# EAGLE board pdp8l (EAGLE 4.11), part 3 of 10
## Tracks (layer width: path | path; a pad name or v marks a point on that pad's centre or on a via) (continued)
F_SET  (via drill 0.61) (continued)
  Route15 0.203: v196.7,124.61 v196.7,126.24 | v351.94,103.89 335.28,120.55 335.28,120.95 334.87,121.36 333.65,121.36 329.59,125.42 329.59,127.05 327.15,129.49 327.15,133.55 321.46,139.24 319.84,139.24 302.77,156.31 302.36,156.31 301.95,156.72 301.95,157.94 v287.73,172.16
  Bottom 0.203: v355.19,50.65 351.54,50.65 D09.F1 | C07.N2 369.42,102.26 365.76,102.26 364.95,103.07 362.1,103.07 360.88,104.29 C08.M2 359.66,104.7 359.26,104.29 355.6,104.29 354.79,103.48 352.35,103.48 v351.94,103.89 | v196.7,124.61 196.29,125.02 128.83,125.02 126.39,122.58 109.32,122.58 108.51,121.77 104.04,121.77 103.63,121.36 C28.F2 | v196.7,126.24 197.1,125.83 239.37,125.83 v242.21,128.68
F_SET\  (via drill 0.61)
  Top 0.203: D17.S2 245.47,22.61 245.47,23.01 243.43,25.04 D17.R2 243.43,25.86 244.65,27.08 244.65,49.02 v247.09,51.46 | v372.67,107.14 372.67,105.51 C07.M2
  Route2 0.203: v332.03,125.02 331.22,124.21 329.18,124.21 C11.E1 327.96,123.39 326.75,122.17 324.71,122.17 321.06,118.52 318.62,118.52 318.21,118.11 318.21,117.7 312.93,112.42 308.86,112.42 303.17,106.73 301.55,106.73 288.95,94.13 288.95,93.32 v247.09,51.46
  Route15 0.203: v332.03,125.02 335.69,125.02 v353.16,107.54
  Bottom 0.203: v353.16,107.54 353.97,106.73 365.35,106.73 367.79,109.17 370.64,109.17 v372.67,107.14
FEED_HOLE  (via drill 0.61)
  Top 0.203: v60.96,142.9 61.77,143.71 v61.77,150.22
  Route2 0.203: v60.96,142.9 60.96,142.49 57.3,138.84 57.3,138.02 56.9,137.62 56.9,135.59 27.23,105.92 27.23,102.26 C34.N2 | v61.77,150.22 62.18,150.22 79.25,167.28 79.25,169.72 80.47,170.94 AB30.BM2
FETCH  (via drill 0.61)
  Top 0.203: B09.B1 350.32,199.39 350.32,194.11 B09.D1 351.13,192.89 352.75,191.26 352.75,190.04 355.19,187.6 | 355.19,187.6 355.19,192.07 354.38,192.89 354.38,196.14 B09.C1 353.57,197.36 353.57,202.64 B09.A1 353.97,203.86 v353.97,216.05 | 355.19,187.6 355.19,181.1 358.44,177.85 358.44,164.85 359.26,164.03 359.26,160.38 358.44,159.56 358.44,136.4 359.66,135.18 359.66,132.74 358.85,131.93 358.85,115.27 361.7,112.42 361.7,99.82 360.88,99.01 C08.P2 | v314.55,216.05 314.15,216.46 314.15,255.88 313.33,256.69 A12.F1
  Bottom 0.203: v353.97,216.05 v314.55,216.05
FETCH\  (via drill 0.61)
  Route2 0.203: v366.17,103.07 362.92,103.07 358.04,98.2 358.04,96.98 357.63,96.57 357.63,95.76 C08.R2
  Bottom 0.203: v366.17,103.07 376.73,103.07 379.98,99.82 411.68,99.82 412.09,100.23 447.04,100.23 448.67,98.6 C01.P2
GND  (via drill 0.61)
  Top 0.508: v441.35,64.47 441.35,83.16 440.54,83.97 440.54,88.04 440.13,88.44 C02.T1 | D16.C2 258.47,59.59 258.47,54.71 D16.E2 258.88,53.49 258.88,49.84 261.31,47.4 261.31,44.96 D16.J1 261.72,43.74 260.5,42.52 260.5,37.24 260.1,36.83 | 260.1,36.83 258.88,35.61 D16.M2 | 263.35,29.11 260.1,29.11 260.1,36.83 | 263.35,29.11 264.57,29.11 D16.P1 | 263.35,29.11 263.35,20.98 262.13,19.76 D16.T1 | C04.P1 417.37,97.79 415.75,96.16 415.75,93.73 414.53,92.51 414.53,89.66 C04.T1 | C06.J1 388.52,114.86 388.52,117.3 387.3,118.52 387.3,124.61 386.08,125.83 386.08,129.49 C06.C2 | C04.C2 410.87,129.49 410.87,124.61 C04.E2 411.68,123.39 412.5,122.58 412.5,116.48 414.12,114.86 C04.J1 414.12,113.64 412.9,112.42 412.9,107.14 411.28,105.51 C04.M2 411.68,104.29 411.68,100.23 v412.5,99.42 | AB02.BD1 439.73,192.89 439.73,188.01 AB02.BF1 | AB02.BE2 436.47,191.26 436.47,196.14 AB02.BC2 | AB07.BD1 375.92,192.89 375.92,188.01 AB07.BF1 | AB07.BC2 372.67,196.14 372.67,191.26 AB07.BE2 | AB06.BF2 383.24,187.6 385.27,189.64 385.27,190.04 AB06.BE2 385.67,191.26 385.67,196.14 AB06.BC2 | AB05.BB2 395.83,200.61 396.65,201.42 397.46,201.42 398.27,200.61 398.27,197.36 AB05.BC2 398.27,196.14 398.27,191.26 AB05.BE2 | AB05.BD1 401.52,192.89 401.52,188.01 AB05.BF1 | AB03.BC2 423.47,196.14 423.47,191.26 AB03.BE2 | AB04.BF1 414.93,186.79 416.97,184.76 AB04.BH1 416.97,183.54 415.75,182.32 415.75,172.97 414.53,171.75 414.53,168.91 AB04.BN1 | AB04.BC2 410.87,196.14 410.87,191.26 AB04.BE2 | AB05.BH1 405.59,184.35 407.62,186.38 407.62,186.79 AB04.BF2 | AB05.BN1 401.12,167.69 401.12,163.63 400.3,162.81 400.3,159.97 401.52,158.75 401.52,156.31 AB05.BT1
  Top 0.508: C12.C2 310.08,130.71 310.9,131.52 310.9,144.12 310.49,144.53 310.49,151.03 312.52,153.06 312.52,155.09 B12.T1 | v327.56,61.62 327.15,62.03 327.15,84.38 325.93,85.6 325.93,88.44 C11.T1 | B36.R2 1.22,162.41 1.22,167.69 B36.N2 1.22,168.91 1.22,174.19 B36.L2 1.22,175.41 1.22,180.29 B36.J2 1.22,181.51 1.22,186.79 B36.F2 | B36.N1 7.72,167.69 7.72,162.41 B36.R1 7.72,161.19 7.72,156.31 B36.T1 8.53,155.09 8.94,154.69 8.94,151.03 10.97,149 10.97,137.21 C36.A1 10.97,135.99 10.97,130.71 C36.C1 10.97,129.49 9.35,127.86 9.35,125.42 8.13,124.21 8.13,121.36 C36.F1 | B35.F2 13.82,186.79 13.82,181.51 B35.J2 | B34.N2 26.42,167.69 26.42,162.41 B34.R2 | B35.T1 20.32,156.31 20.32,161.19 B35.R1 | B35.N2 13.82,167.69 13.82,162.41 B35.R2 | B34.L2 26.82,175.41 26.82,180.29 B34.J2 26.42,181.51 26.42,186.79 B34.F2 | B33.J2 39.42,180.29 39.42,175.41 B33.L2 39.42,174.19 39.42,168.91 B33.N2 | B34.K1 36.98,178.26 39.01,180.29 39.01,180.7 B33.J2 | B34.T1 32.92,156.31 32.92,161.19 B34.R1 32.92,162.41 32.92,167.69 B34.N1 | B33.F2 39.42,186.79 39.42,181.51 B33.J2 | B32.T1 58.93,156.31 58.93,161.19 B32.R1 58.52,162.41 58.52,167.69 B32.N1 58.93,168.91 60.15,170.13 60.15,175.41 61.77,177.04 B32.K1 | B33.T1 45.92,156.31 45.92,161.19 B33.R1 45.52,162.41 45.52,167.69 B33.N1 | B32.N2 52.02,168.91 52.02,174.19 B32.L2 52.02,175.41 52.02,180.29 B32.J2 52.02,181.51 52.02,186.79 B32.F2 | B28.D2 102.82,192.89 102.82,188.01 B28.F2 | B36.A1 10.57,202.64 10.57,197.36 B36.C1 10.97,196.14 10.97,195.73 9.75,194.51 9.75,189.64 8.13,188.01 B36.F1 | B35.A1 23.57,202.64 23.57,197.36 B35.C1
  Top 0.508: B32.A1 61.77,202.64 61.77,197.36 B32.C1 | B33.C1 48.77,197.36 48.77,202.64 B33.A1 49.17,203.86 49.17,215.24 47.55,216.86 47.55,224.18 46.74,224.99 A33.T1 | B34.A1 36.17,202.64 36.17,197.36 B34.C1 | 120.7,36.83 119.48,35.61 D27.M2 | 120.7,36.83 120.7,42.52 121.92,43.74 D27.J1 | D28.V1 110.13,13.26 112.17,15.29 D28.U1 | 110.95,17.73 112.17,16.51 112.17,16.1 D28.U1 | 110.95,17.73 110.13,18.54 D28.T1 | 110.95,17.73 110.95,26.26 112.57,27.89 D28.P1 | D27.T2 115.42,18.54 113.39,16.51 113.39,16.1 D28.U1 | D27.V1 122.73,13.26 124.77,15.29 124.77,15.7 D27.U1 124.77,16.1 124.77,16.51 123.55,17.73 | 123.55,17.73 122.73,18.54 D27.T1 | 123.55,17.73 123.55,26.26 125.17,27.89 D27.P1 125.17,29.11 125.17,32.36 120.7,36.83 | v149.15,62.84 149.15,67.31 149.96,68.12 149.96,83.16 148.74,84.38 148.74,88.04 148.34,88.44 C25.T1 | D29.A1 99.57,66.09 99.57,60.81 D29.C1 100.38,59.59 101.6,58.37 101.6,49.02 | D30.A1 86.97,66.09 86.97,60.81 D30.C1 | 101.6,49.02 101.6,42.93 100.38,41.71 D29.K1 | 101.6,49.02 102.82,50.24 D28.F2 | D30.K1 87.78,40.89 89.81,38.86 89.81,38.46 D29.L2 | D29.L2 90.22,38.86 90.22,43.74 D29.J2 90.22,44.96 90.22,50.24 D29.F2 | D30.L2 77.62,38.86 77.62,43.74 D30.J2 77.22,44.96 77.22,50.24 D30.F2 78.44,50.65 83.72,50.65 D30.F1 | D29.T1 96.72,19.76 96.72,24.64 D29.R1 96.32,25.86 96.32,31.14 D29.N1 | D31.T1 71.93,19.36 76.4,19.36 76.4,23.42 77.62,24.64 D30.R2 77.62,25.86 77.62,31.14 D30.N2 | D30.U2 81.69,16.1 83.72,18.14 83.72,18.54 D30.T1 84.12,19.76 84.12,24.64 D30.R1 83.72,25.86 83.72,31.14 D30.N1 | D29.L2 90.22,37.64 90.22,32.36 D29.N2 | D31.C2 68.68,60.81 69.9,62.03 69.9,87.22 71.12,88.44 C31.T1
  Top 0.508: D32.D1 58.93,56.34 60.15,55.12 60.15,20.98 58.93,19.76 D32.T1 58.12,18.54 54.05,18.54 54.05,12.04 53.24,11.23 34.95,11.23 34.95,13.66 31.7,16.92 | D36.U2 5.28,16.51 7.32,18.54 D36.T1 7.72,19.76 7.72,24.64 D36.R1 | D36.R1 7.32,25.04 2.03,25.04 D36.R2 1.22,25.86 1.22,31.14 D36.N2 1.22,32.36 1.22,37.64 D36.L2 1.22,38.86 1.22,43.74 D36.J2 1.22,44.96 1.22,50.24 D36.F2 2.03,51.46 3.25,52.68 3.25,58.37 4.47,59.59 D36.C2 | D36.R1 7.72,25.86 7.72,31.14 D36.N1 8.13,32.36 9.35,33.58 9.35,38.86 10.97,40.49 D36.K1 | 31.7,16.92 32.92,18.14 32.92,18.54 D34.T1 33.33,19.76 33.33,24.64 D34.R1 32.92,25.86 32.92,31.14 D34.N1 | 31.7,16.92 30.89,16.1 D34.U2 | D35.U2 17.88,16.51 19.91,18.54 19.91,18.95 D35.T1 20.32,19.76 20.32,24.64 D35.R1 19.91,25.04 15.04,25.04 D35.R2 13.82,25.86 13.82,31.14 D35.N2 | D35.J2 14.22,43.74 14.22,38.86 D35.L2 13.82,37.64 13.82,32.36 D35.N2 | D35.N2 15.04,31.55 19.91,31.55 D35.N1 | D34.N2 26.82,31.14 26.82,25.86 D34.R2 | D34.A1 36.17,66.09 36.17,60.81 D34.C1 | D36.A1 10.57,66.09 10.57,60.81 D36.C1 | D35.C1 23.57,60.81 23.57,66.09 D35.A1 23.57,67.31 17.88,73 17.88,85.19 C35.U2 17.88,86.41 19.91,88.44 19.91,88.85 C35.T1 20.32,89.66 20.32,94.54 C35.R1 | D34.L2 26.42,38.46 24.38,40.49 24.38,40.89 D35.K1 24.38,41.71 24.38,42.11 26.42,44.15 D34.J2 26.42,44.96 26.42,50.24 D34.F2 | D34.K1 36.17,41.71 34.95,42.93 34.95,49.02 33.73,50.24 D34.F1 | C35.A1 23.57,135.99 23.57,130.71 C35.C1 | C36.F2 1.22,120.14 1.22,114.86 C36.J2 1.63,113.64 1.63,108.76 C36.L2 1.63,107.14 1.63,102.26 C36.N2 1.22,101.04 1.22,95.76 C36.R2 2.03,94.94 7.32,94.94 C36.R1
  Top 0.508: C36.N1 7.72,101.04 7.72,95.76 C36.R1 | C36.T1 7.72,89.66 7.72,94.54 C36.R1 | C35.N2 14.22,102.26 14.22,107.14 C35.L2 13.82,108.36 11.79,110.39 11.79,110.79 C36.K1 11.79,111.61 13.82,113.64 C35.J2 13.82,114.86 13.82,120.14 C35.F2 | 124.36,84.78 124.77,85.19 124.77,85.6 C27.U1 124.77,86 124.77,86.41 122.73,88.44 C27.T1 122.33,89.66 122.33,91.29 125.17,94.13 125.17,97.79 C27.P1 | 124.36,84.78 122.73,83.16 C27.V1 | C27.M2 119.48,105.51 120.7,106.73 120.7,109.98 121.92,111.2 121.92,113.64 C27.J1 121.92,114.86 121.11,115.67 121.11,118.11 119.48,119.74 119.48,123.39 C27.E2 119.08,124.61 119.08,129.49 C27.C2 | B24.T1 159.72,155.09 158.5,153.87 158.5,131.52 157.68,130.71 C24.C2 | 124.36,84.78 124.36,80.72 123.95,80.31 123.95,61.62 124.77,60.81 D27.C1 | AB05.AB2 395.83,269.29 397.87,267.26 AB05.AC2 | AB06.AB2 383.24,269.7 385.27,267.67 385.27,267.26 AB06.AC2 | AB07.AB2 370.23,269.29 372.26,267.26 372.26,266.85 AB07.AC2 | A10.J1 337.72,251.41 336.91,252.22 336.91,256.29 336.5,256.69 336.5,264.82 335.28,266.04 A10.C2 | 247.9,242.47 249.12,243.69 A17.L1 | 247.9,242.47 247.9,227.43 249.12,226.21 A17.T1 | 247.9,242.47 247.9,264.41 246.28,266.04 A17.C2 | A28A.E2 105.66,260.76 103.63,262.79 103.63,263.2 A28A.D2 103.63,264.01 103.63,264.41 105.66,266.45 A28A.C2 | A25.E2 145.09,260.76 149.15,260.76 154.84,266.45 156.46,266.45 A24.C2 157.68,266.45 159.72,264.41 159.72,264.01 A24.D1 160.12,262.79 158.9,261.57 158.9,246.13 | 158.9,246.13 158.9,245.72 159.72,244.91 A24.L1 | 156.06,240.44 156.46,240.84 A24.M2 | 156.06,240.44 154.43,238.81 A24.N2 154.43,237.59 155.65,236.37 155.65,232.31 160.12,227.84 160.12,226.21 A24.T1 159.72,224.99 159.72,222.56 155.65,218.49 155.65,198.58 156.06,198.17
  Top 0.508: 156.06,198.17 156.87,197.36 B24.C2 | 158.9,246.13 152.4,246.13 152.4,244.09 156.06,240.44 | B17.J1 248.72,181.51 247.5,182.73 247.5,191.67 245.87,193.29 245.87,196.14 B17.C2 | A20.T1 211.73,224.99 215.8,224.99 215.8,208.33 208.48,201.02 208.48,197.36 B20.C2 | 156.06,198.17 v150.37,192.48
  Route2 0.508: B34.U2 30.89,152.65 30.89,153.06 32.92,155.09 B34.T1 | B33.U2 43.48,152.65 43.48,153.06 45.52,155.09 B33.T1 | C27.F2 116.64,120.95 116.64,121.36 118.67,123.39 C27.E2
  Route15 0.508: AB07.BH1 378.76,184.35 378.76,184.76 376.73,186.79 AB07.BF1 | D27.F2 116.23,50.24 116.23,48.21 118.26,46.18 119.89,46.18 121.51,44.55 D27.J1 | D32.C2 55.68,59.59 56.08,59.59 58.12,57.56 D32.D1 59.33,57.15 60.15,56.34 63.8,60 67.46,60 D31.C2 | A17.M1 251.97,241.66 251.56,241.66 249.53,243.69 A17.L1 | AB07.BC2 372.26,196.95 372.26,197.36 370.23,199.39 AB07.BB2
  Bottom 0.508: D01.T1 451.92,18.54 451.1,17.73 441.76,17.73 440.54,18.95 D02.T1 439.32,18.54 438.51,17.73 412.9,17.73 | 323.49,17.73 314.15,17.73 313.33,18.54 D12.T1 312.12,18.54 311.71,18.14 307.64,18.14 307.24,17.73 305.61,17.73 304.39,18.95 300.74,18.95 D13.T1 299.52,18.54 299.11,18.14 295.05,18.14 294.64,17.73 286.11,17.73 | 323.49,17.73 324.71,18.95 D11.T1 | 336.91,17.73 337.72,18.54 D10.T1 | 323.49,17.73 336.91,17.73 | 349.5,17.73 350.32,18.54 D09.T1 | 336.91,17.73 349.5,17.73 | 362.1,17.73 362.92,18.54 D08.T1 | 349.5,17.73 362.1,17.73 | 374.29,17.73 375.51,18.95 D07.T1 | 362.1,17.73 374.29,17.73 | 387.71,17.73 388.52,18.54 D06.T1 | 374.29,17.73 387.71,17.73 | 400.3,17.73 401.12,18.54 D05.T1 | 387.71,17.73 400.3,17.73 | 412.9,17.73 413.71,18.54 D04.T1 | 400.3,17.73 412.9,17.73 | C02.T1 440.54,89.26 444.19,89.26 445.41,90.47 450.7,90.47 451.92,89.26 C01.T1 | 441.35,61.21 441.76,61.21 442.16,61.62 447.85,61.62 448.67,60.81 D01.C2 | 441.35,61.21 438.1,61.21 437.29,60.4 D02.C2 436.07,60.81 435.66,61.21 431.6,61.21 431.19,61.62 425.09,61.62 424.28,60.81 CD03.BC2 423.06,60.4 421.03,60.4 419.81,61.62 416.56,61.62 416.15,61.21 412.09,61.21 411.68,60.81 D04.C2 410.46,60.4 407.62,60.4 406.4,61.62 403.96,61.62 403.56,61.21 399.49,61.21 399.08,60.81 D05.C2 397.87,60.81 393.8,60.81 392.99,61.62 391.36,61.62 390.96,61.21 387.3,61.21 386.49,60.4 D06.C2 385.27,60.81 384.86,61.21 380.8,61.21 380.39,61.62 377.14,61.62 376.33,60.81 373.48,60.81 D07.C2 372.26,60.4 371.45,61.21 368.2,61.21 367.79,61.62 365.35,61.62 364.13,60.4 360.88,60.4 D08.C2 359.66,60.4 358.44,61.62 349.1,61.62 348.29,60.81 D09.C2 347.07,60.81 346.25,61.62 336.91,61.62
  Bottom 0.508: 441.35,61.21 v441.35,64.47 | 336.91,61.62 335.69,60.4 D10.C2 | 336.91,61.62 v327.56,61.62 327.15,61.21 323.09,61.21 322.68,60.81 D11.C2 321.46,60.4 320.65,61.21 317.4,61.21 316.99,61.62 313.74,61.62 312.93,60.81 310.08,60.81 D12.C2 308.86,60.4 308.05,61.21 304.39,61.21 303.99,61.62 301.14,61.62 300.33,60.81 297.49,60.81 D13.C2 296.27,60.81 292.2,60.81 291.39,61.62 289.76,61.62 289.36,61.21 285.7,61.21 284.89,60.4 D14.C2 283.67,60.81 283.26,61.21 279.2,61.21 278.79,61.62 275.54,61.62 274.73,60.81 271.88,60.81 D15.C2 270.66,60.4 269.85,61.21 266.6,61.21 266.19,61.62 262.94,61.62 262.13,60.81 259.28,60.81 D16.C2 258.06,60.4 254.81,60.4 253.59,61.62 247.5,61.62 246.69,60.81 D17.C2 245.47,60.81 244.65,61.62 232.05,61.62 | D17.T1 249.94,18.95 254.81,18.95 D16.T2 256.03,18.54 261.31,18.54 D16.T1 262.53,18.54 263.35,17.73 272.69,17.73 | 272.69,17.73 273.91,18.95 D15.T1 | 286.11,17.73 286.92,18.54 D14.T1 | 272.69,17.73 286.11,17.73 | 232.05,61.62 221.89,61.62 221.08,60.81 D19.C2 | 232.05,61.62 232.87,60.81 D18.C2 | C04.T1 413.71,88.44 408.43,88.44 C04.T2 407.21,88.85 402.34,88.85 C05.T1 401.12,88.85 398.68,88.85 397.05,90.47 390.96,90.47 389.74,89.26 C06.T1 388.52,89.26 387.3,90.47 377.95,90.47 376.73,89.26 C07.T1 375.51,89.26 371.86,89.26 370.64,90.47 367.79,90.47 366.57,89.26 364.13,89.26 C08.T1 362.92,89.26 362.51,89.66 358.44,89.66 357.63,90.47 355.19,90.47 353.97,89.26 351.54,89.26 C09.T1 350.32,89.26 346.66,89.26 345.44,90.47 343.81,90.47 343,89.66 339.34,89.66 338.94,89.26 C10.T1 337.72,89.26 334.87,89.26 333.65,90.47 327.15,90.47 325.93,89.26 C11.T1 324.71,89.26 322.68,89.26 321.46,90.47 318.62,90.47 318.21,90.07 314.15,90.07 313.33,89.26 C12.T1 312.12,89.26 309.68,89.26 308.46,90.47 306.02,90.47 305.61,90.07 301.55,90.07 300.74,89.26 C13.T1 299.52,89.26 295.86,89.26 294.64,90.47 289.36,90.47 288.14,89.26 C14.T1 286.92,89.26 283.67,89.26 282.45,90.47 276.35,90.47 275.13,89.26 C15.T1 273.91,89.26 272.69,90.47 267.82,90.47 267,89.66 262.94,89.66 262.53,89.26 C16.T1
  Bottom 0.508: C19.C2 221.08,130.71 221.89,131.52 232.05,131.52 232.87,130.71 C18.C2 234.09,130.3 235.31,131.52 241,131.52 242.21,130.3 245.47,130.3 C17.C2 246.69,130.71 247.5,131.52 256.85,131.52 258.06,130.3 C16.C2 259.28,129.9 260.5,128.68 265.79,128.68 266.6,129.49 270.26,129.49 270.66,129.9 C15.C2 271.88,130.71 275.95,130.71 276.76,131.52 278.79,131.52 279.6,130.71 283.67,130.71 C14.C2 284.89,130.3 285.7,131.12 289.36,131.12 289.76,131.52 291.39,131.52 292.2,130.71 296.27,130.71 C13.C2 297.49,130.71 297.89,131.12 301.95,131.12 302.36,131.52 306.02,131.52 307.24,130.3 308.86,130.3 C12.C2 310.08,130.71 310.9,131.52 318.21,131.52 319.43,130.3 321.46,130.3 C11.C2 322.68,130.3 326.34,130.3 327.56,131.52 330.81,131.52 332.03,130.3 334.47,130.3 C10.C2 335.69,130.3 336.5,131.12 340.16,131.12 340.56,131.52 346.25,131.52 | 346.25,131.52 347.07,130.71 C09.C2 | 346.25,131.52 354.79,131.52 355.19,131.12 358.85,131.12 359.66,130.3 C08.C2 360.88,129.9 364.13,129.9 365.35,128.68 371.04,128.68 | 371.04,128.68 372.26,129.9 C07.C2 | 371.04,128.68 384.05,128.68 385.27,129.9 C06.C2 386.49,129.9 387.71,128.68 400.3,128.68 | 400.3,128.68 399.08,129.9 C05.C2 | 400.3,128.68 405.59,128.68 407.21,127.05 C04.D2 408.03,126.24 408.43,126.24 410.46,124.21 C04.E2 | 421.84,128.68 423.06,129.9 CD03.AC2 | 421.84,128.68 412.9,128.68 411.68,129.9 C04.C2 | 421.84,128.68 434.85,128.68 436.07,129.9 C02.C2 437.29,130.3 438.51,131.52 447.85,131.52 448.67,130.71 C01.C2 | v412.5,99.42 416.56,99.42 416.97,99.01 C04.P1 | AB03.BH1 430.78,183.95 431.19,183.54 434.85,183.54 435.66,182.73 440.94,182.73 442.16,183.95 AB02.BH1 442.57,184.76 442.16,184.76 440.13,186.79 AB02.BF1 439.32,188.01 438.91,188.01 436.88,190.04 AB02.BE2 436.07,190.04 435.66,190.04 433.63,188.01 AB02.BF2 432.82,186.79 427.53,186.79 AB03.BF1 426.31,187.2 424.28,187.2
  Bottom 0.508: AB04.BB2 408.43,199.39 408.84,198.98 412.9,198.98 413.31,198.58 419,198.58 419.81,199.39 420.22,199.39 AB03.BB2 421.44,199.8 422.25,198.98 425.91,198.98 426.31,198.58 434.44,198.58 | 434.85,198.17 435.66,197.36 436.07,197.36 AB02.BC2 | 434.85,198.17 434.44,198.58 | 434.44,198.58 433.63,199.39 AB02.BB2 | 434.85,198.17 447.85,198.17 448.67,197.36 B01.C2 | AB07.BF2 370.23,188.01 372.26,190.04 372.67,190.04 AB07.BE2 373.48,190.04 373.89,190.04 375.92,188.01 AB07.BF1 376.73,186.79 382.02,186.79 AB06.BF2 | AB06.BB2 382.02,199.8 381.61,199.39 377.95,199.39 375.92,197.36 373.48,197.36 AB07.BC2 | AB06.BC2 386.08,196.14 388.11,194.11 388.52,194.11 AB06.BD1 | AB06.BE2 386.08,190.04 386.49,190.04 388.52,188.01 AB06.BF1 389.74,187.2 394.61,187.2 AB05.BF2 395.43,188.01 397.46,190.04 397.87,190.04 AB05.BE2 399.08,190.04 399.49,190.04 401.52,188.01 AB05.BF1 402.34,187.2 407.21,187.2 AB04.BF2 408.43,188.01 410.46,190.04 AB04.BE2 | 424.28,187.2 421.44,187.2 AB03.BF2 420.22,186.79 414.93,186.79 AB04.BF1 414.12,188.01 412.09,190.04 411.68,190.04 AB04.BE2 | 424.28,187.2 424.28,190.04 AB03.BE2 424.28,190.86 424.69,190.86 426.72,192.89 AB03.BD1 | AB06.BH1 392.58,183.54 393.39,182.73 400.71,182.73 401.52,183.54 404.37,183.54 AB05.BH1 | AB04.BD1 414.12,192.89 412.09,190.86 411.68,190.86 AB04.BE2 | 221.89,154.28 212.55,154.28 211.73,155.09 B20.T1 | 221.89,154.28 223.11,155.5 B19.T1 | 235.31,154.28 236.12,155.09 B18.T1 | 235.31,154.28 221.89,154.28 | 235.31,154.28 247.9,154.28 248.72,155.09 B17.T1 249.94,155.5 251.16,154.28 260.5,154.28 | 260.5,154.28 261.31,155.09 B16.T1
  Bottom 0.508: 272.69,154.28 273.91,155.5 B15.T1 | 272.69,154.28 260.5,154.28 | 272.69,154.28 282.04,154.28 283.26,155.5 286.92,155.5 B14.T1 288.14,155.5 288.95,155.5 290.17,154.28 298.7,154.28 299.52,155.09 B13.T1 300.74,155.5 301.95,154.28 310.08,154.28 310.9,155.09 312.12,155.09 B12.T1 313.33,155.09 314.15,154.28 323.49,154.28 324.71,155.5 B11.T1 325.93,155.09 326.75,154.28 334.06,154.28 335.28,155.5 337.72,155.5 B10.T1 338.94,155.5 340.16,154.28 349.5,154.28 | AB07.BN2 370.64,168.1 375.51,168.1 AB07.BN1 376.73,167.69 382.02,167.69 AB06.BN2 383.24,168.1 388.52,168.1 AB06.BN1 389.74,168.1 394.61,168.1 AB05.BN2 395.83,167.69 401.12,167.69 AB05.BN1 402.34,168.1 407.21,168.1 AB04.BN2 408.43,168.1 413.71,168.1 AB04.BN1 414.93,168.1 420.22,168.1 AB03.BN2 421.44,168.1 426.31,168.1 AB03.BN1 427.53,167.69 432.82,167.69 AB02.BN2 434.04,168.1 439.32,168.1 AB02.BN1 | B01.T1 451.92,155.09 449.07,155.09 448.26,154.28 441.76,154.28 440.54,155.5 AB02.BT1 439.32,155.09 438.91,154.69 434.85,154.69 434.44,154.28 428.35,154.28 427.53,155.09 AB03.BT1 426.31,155.5 425.09,154.28 415.75,154.28 414.93,155.09 AB04.BT1 413.71,155.09 410.87,155.09 410.06,154.28 403.56,154.28 402.34,155.5 AB05.BT1 401.12,155.09 397.05,155.09 396.24,154.28 392.99,154.28 391.77,155.5 389.74,155.5 AB06.BT1 388.52,155.09 387.71,154.28 374.29,154.28 | 349.5,154.28 350.32,155.09 B09.T1 | 362.1,154.28 362.92,155.09 B08.T1 | 349.5,154.28 362.1,154.28 | 374.29,154.28 375.51,155.5 AB07.BT1 | 362.1,154.28 374.29,154.28 | B36.U2 4.88,153.06 6.91,155.09 7.32,155.09 B36.T1 | B36.R2 2.03,162 7.32,162 B36.R1 8.53,161.59 13.82,161.59 B35.R2 15.04,161.59 19.91,161.59 B35.R1 21.13,161.59 26.42,161.59 B34.R2
  Bottom 0.508: B36.F2 2.03,186.79 7.32,186.79 B36.F1 8.53,187.2 13.82,187.2 B35.F2 15.04,187.2 19.91,187.2 B35.F1 | 13.01,179.48 13.82,180.29 B35.J2 | 13.01,179.48 11.79,178.26 B36.K1 11.38,177.04 11.79,177.04 13.82,175.01 B35.L2 | 13.01,179.48 21.95,179.48 23.16,178.26 B35.K1 | B35.N2 15.04,168.1 19.91,168.1 B35.N1 | B35.U2 17.88,153.06 19.91,155.09 20.32,155.09 B35.T1 | B33.F2 39.01,187.2 34.14,187.2 B34.F1 32.92,187.2 27.64,187.2 B34.F2 | B33.R2 39.01,161.59 34.14,161.59 B34.R1 | B34.N2 27.64,168.1 32.92,168.1 B34.N1 34.14,168.1 39.01,168.1 B33.N2 40.23,168.1 45.52,168.1 B33.N1 46.74,168.1 51.61,168.1 B32.N2 52.83,168.1 58.12,168.1 B32.N1 | 69.49,154.28 70.71,155.5 AB31.BT1 | 69.49,154.28 60.15,154.28 59.33,155.09 B32.T1 | 69.49,154.28 78.84,154.28 79.25,154.69 83.31,154.69 83.72,155.09 AB30.BT1 | B33.F1 46.74,187.2 51.61,187.2 B32.F2 52.83,186.79 58.12,186.79 B32.F1 | B33.U2 43.48,152.25 43.89,151.84 47.55,151.84 48.36,151.03 53.65,151.03 54.86,152.25 B32.U2 | B33.K1 49.58,178.26 51.61,180.29 52.02,180.29 B32.J2 | B32.R2 51.61,162 46.74,162 B33.R1 | AB30.AT1 83.72,224.99 82.5,223.77 76,223.77 74.78,224.99 71.93,224.99 AB31.AT1 70.71,225.81 68.28,225.81 67.06,227.03 60.55,227.03 59.33,225.81 A32.T1 58.12,225.4 55.27,225.4 53.24,227.43 49.99,227.43 48.36,225.81 46.74,225.81 A33.T1 45.52,225.81 44.3,227.03 35.76,227.03 34.14,225.4 A34.T1 32.92,225.81 28.85,225.81 27.64,227.03 22.35,227.03 21.13,225.81 A35.T1 19.91,225.81 18.69,227.03 9.75,227.03 8.53,225.81 A36.T1 | 104.85,195.33 105.66,196.14 106.07,196.14 B28.C2 | 104.85,195.33 103.63,194.11 B28.D2
  Bottom 0.508: B28.H2 106.07,184.76 104.04,186.79 103.63,186.79 B28.F2 103.63,188.01 105.66,190.04 B28.E2 106.88,190.04 108.1,188.82 130.05,188.82 131.27,190.04 B26.E2 132.49,190.86 132.89,191.26 136.55,191.26 137.36,192.07 149.56,192.07 149.96,192.48 v150.37,192.48 | 104.85,195.33 95.5,195.33 94.28,196.54 AB29.BC2 93.07,196.95 91.85,196.95 90.22,195.33 82.91,195.33 81.69,196.54 AB30.BC2 80.47,197.36 80.06,197.76 76,197.76 75.59,198.17 72.34,198.17 71.53,197.36 68.68,197.36 AB31.BC2 67.46,196.54 62.59,196.54 B32.C1 61.37,196.54 56.08,196.54 B32.C2 54.86,196.54 49.99,196.54 B33.C1 48.77,196.95 43.48,196.95 B33.C2 42.27,196.54 36.98,196.54 B34.C1 35.76,196.54 30.89,196.54 B34.C2 29.67,196.54 24.38,196.54 B35.C1 23.16,196.54 17.88,196.54 B35.C2 16.66,196.54 11.79,196.54 B36.C1 10.57,196.54 5.28,196.54 B36.C2 | D28.J1 110.13,44.15 110.95,43.33 115.01,43.33 115.42,42.93 120.29,42.93 121.51,44.15 D27.J1 | D25.T1 147.12,18.54 145.9,17.32 127.2,17.32 125.98,16.1 D27.U1 | D27.T2 116.64,18.95 121.51,18.95 D27.T1 | 149.15,61.62 151.99,61.62 153.21,60.4 156.46,60.4 D24.C2 157.68,60.81 160.53,60.81 161.34,61.62 164.59,61.62 165,61.21 168.25,61.21 169.06,60.4 D23.C2 | 149.15,61.62 145.9,61.62 145.09,60.81 D25.C2 143.87,60.81 143.05,61.62 126.8,61.62 125.98,60.81 D27.C1 124.77,60 119.48,60 D27.C2 118.26,60 113.39,60 D28.C1 112.17,60 106.88,60 D28.C2 105.66,60 100.79,60 D29.C1 99.57,60 94.28,60 D29.C2 93.07,60 87.78,60 D30.C1 86.56,60 81.69,60 D30.C2 | 149.15,61.62 v149.15,62.84 | D28.F2 102.41,50.65 97.54,50.65 D29.F1 96.32,50.24 91.03,50.24 D29.F2 89.81,50.65 84.94,50.65 D30.F1
  Bottom 0.508: D29.T1 97.54,18.95 102.41,18.95 D28.T2 103.63,18.54 108.92,18.54 D28.T1 | D28.M2 105.66,34.8 104.04,33.17 99.16,33.17 97.94,31.95 97.54,31.95 D29.N1 96.32,31.14 91.03,31.14 D29.N2 89.81,31.55 84.94,31.55 D30.N1 83.72,31.55 78.44,31.55 D30.N2 | D29.U2 93.07,16.1 92.66,16.51 89,16.51 86.56,18.95 84.94,18.95 D30.T1 | D29.R2 89.81,25.04 84.94,25.04 D30.R1 | C32.T1 59.33,88.44 60.55,87.22 69.09,87.22 70.71,88.85 C31.T1 | D34.R2 26.42,25.04 21.13,25.04 D35.R1 | D34.N1 32.92,31.55 27.64,31.55 D34.N2 | D36.N1 8.53,31.55 13.82,31.55 D35.N2 | D33.C2 42.27,60 36.98,60 D34.C1 35.76,60 30.89,60 D34.C2 29.67,60 24.38,60 D35.C1 23.16,60 17.88,60 D35.C2 16.66,60 11.79,60 D36.C1 10.57,60 5.28,60 D36.C2 | D34.F1 32.92,50.65 27.64,50.65 D34.F2 26.42,50.24 21.13,50.24 D35.F1 19.91,50.65 15.04,50.65 D35.F2 13.82,50.24 8.53,50.24 D36.F1 7.32,50.65 2.03,50.65 D36.F2 | C36.C2 5.28,129.9 10.57,129.9 C36.C1 11.79,129.9 16.66,129.9 C35.C2 17.88,129.9 23.16,129.9 C35.C1 24.38,130.71 25.2,131.52 34.54,131.52 35.76,130.3 C34.C1 36.98,129.9 42.27,129.9 C33.C2 43.48,130.71 43.89,131.12 47.95,131.12 48.36,131.52 51.21,131.52 52.43,130.3 54.86,130.3 C32.C2 56.08,129.9 57.3,128.68 66.24,128.68 | C35.R1 19.91,94.94 15.04,94.94 C35.R2 13.82,94.94 8.53,94.94 C36.R1 | C34.T1 32.92,88.44 28.85,88.44 27.64,87.22 22.35,87.22 21.13,88.44 C35.T1 | C36.F1 7.32,120.14 2.03,120.14 C36.F2 | C36.U2 4.88,86.41 6.91,88.44 7.32,88.44 C36.T1 | C35.F2 15.04,120.55 19.91,120.55 C35.F1 | C35.N1 19.91,101.45 15.04,101.45 C35.N2 13.82,101.04 8.53,101.04 C36.N1 | C35.K1 23.16,110.79 21.95,109.58 16.26,109.58 15.04,108.36 C35.L2
  Bottom 0.508: 66.24,128.68 67.46,129.9 C31.C2 | 79.25,128.68 80.47,129.9 C30.C2 | 66.24,128.68 79.25,128.68 | 91.85,128.68 93.07,129.9 C29.C2 | 79.25,128.68 91.85,128.68 | 91.85,128.68 104.44,128.68 105.66,129.9 C28.C2 106.88,130.71 107.7,131.52 117.04,131.52 118.26,130.3 C27.C2 119.48,129.9 124.77,129.9 C27.C1 125.98,129.9 131.27,129.9 C26.C2 132.49,130.3 133.71,131.52 143.05,131.52 | C28.T1 110.13,88.44 115.42,88.44 C27.T2 116.64,88.85 121.51,88.85 C27.T1 | B24.T1 160.93,155.09 165,155.09 165.81,154.28 170.28,154.28 171.5,155.5 172.31,155.5 B23.T1 | 143.05,131.52 143.87,130.71 C25.C2 | 143.05,131.52 155.25,131.52 156.46,130.3 C24.C2 157.68,129.9 158.9,128.68 167.84,128.68 169.06,129.9 C23.C2 | C27.P1 124.77,98.6 124.36,99.01 122.73,99.01 119.48,102.26 119.48,104.29 C27.M2 | 295.45,268.07 286.11,268.07 284.89,266.85 A14.C2 283.67,267.26 282.85,268.07 273.1,268.07 272.29,267.26 271.88,267.26 A15.C2 270.66,266.85 269.85,267.67 266.6,267.67 266.19,268.07 263.35,268.07 262.53,267.26 259.28,267.26 A16.C2 258.06,266.45 254.81,266.45 253.59,265.23 247.9,265.23 246.69,266.45 A17.C2 245.47,267.26 241.81,267.26 241,268.07 238.96,268.07 238.15,267.26 234.49,267.26 234.09,266.85 A18.C2 232.87,266.04 232.05,265.23 221.89,265.23 221.08,266.04 A19.C2 219.86,266.85 217.02,266.85 215.8,268.07 213.36,268.07 212.95,267.67 208.89,267.67 208.48,267.26 A20.C2 | 295.45,268.07 296.27,267.26 A13.C2 | 295.45,268.07 303.99,268.07 304.8,267.26 308.46,267.26 308.86,266.85 A12.C2 310.08,266.45 310.49,266.04 314.15,266.04 314.96,265.23 318.21,265.23 319.43,266.45 321.46,266.45 A11.C2 322.68,266.04 323.49,265.23 333.65,265.23
  Bottom 0.508: 409.25,268.48 410.46,267.26 410.87,267.26 AB04.AC2 411.68,267.26 412.9,268.48 421.84,268.48 | 409.25,268.48 408.43,269.29 AB04.AB2 | 409.25,268.48 400.71,268.48 399.08,266.85 AB05.AC2 | 421.84,268.48 423.06,267.26 423.47,267.26 AB03.AC2 424.28,267.26 425.5,268.48 434.44,268.48 | 421.84,268.48 421.03,269.29 AB03.AB2 | 434.85,268.07 435.66,267.26 436.07,267.26 AB02.AC2 | 434.44,268.48 434.85,268.07 | 434.44,268.48 433.63,269.29 AB02.AB2 | 434.85,268.07 447.85,268.07 448.67,267.26 A01.C2 | 333.65,265.23 334.47,266.04 A10.C2 | 345.85,265.23 347.07,266.45 A09.C2 | 333.65,265.23 345.85,265.23 | 345.85,265.23 358.44,265.23 359.66,266.45 A08.C2 360.88,267.26 361.7,268.07 368.2,268.07 368.61,268.48 | 368.61,268.48 369.42,269.29 AB07.AB2 | 368.61,268.48 381.2,268.48 382.02,269.29 AB06.AB2 | AB05.AB2 394.61,269.7 392.99,268.07 388.52,268.07 387.3,266.85 386.49,266.85 AB06.AC2 | 438.1,227.03 428.75,227.03 427.53,225.81 AB03.AT1 426.31,225.81 425.91,226.21 421.84,226.21 421.03,227.03 412.5,227.03 | 438.1,227.03 439.32,225.81 AB02.AT1 | 438.1,227.03 450.7,227.03 451.92,225.81 A01.T1 | 387.3,227.03 377.95,227.03 376.73,225.81 AB07.AT1 375.51,225.81 372.67,225.81 371.45,227.03 369.42,227.03 369.01,226.62 364.95,226.62 364.13,225.81 A08.T1 362.92,225.81 362.51,226.21 358.44,226.21 357.63,227.03 353.16,227.03 351.94,225.81 351.54,225.81 A09.T1 350.32,225.81 346.25,225.81 345.03,227.03 343.81,227.03 343.41,226.62 340.16,226.62 338.94,225.4 A10.T1 337.72,225.81 336.91,226.62 332.84,226.62 332.44,227.03 330,227.03 328.78,225.81 325.93,225.81 A11.T1 324.71,225.81 320.65,225.81 319.43,227.03 318.62,227.03 317.4,225.81 313.33,225.81 A12.T1 312.12,225.81 308.05,225.81 306.83,227.03 304.39,227.03 303.17,225.81 300.74,225.81 A13.T1 299.52,225.81 295.45,225.81 294.23,227.03 293.01,227.03 292.61,226.62 289.36,226.62 288.14,225.4 A14.T1 286.92,225.81 286.11,226.62 282.04,226.62 281.63,227.03 279.2,227.03 277.98,225.81 275.13,225.81 A15.T1 273.91,225.81 271.07,225.81 269.85,227.03 263.75,227.03 262.53,225.81 A16.T1 261.31,225.81 257.25,225.81 256.03,227.03 255.22,227.03 254,225.81 249.94,225.81 A17.T1 248.72,224.99 245.06,224.99 243.84,223.77 242.21,223.77 241.4,224.59 238.15,224.59 237.34,225.4 A18.T1 236.12,224.99 233.27,224.99 232.05,223.77 229.62,223.77 228.8,224.59 224.74,224.59 224.33,224.99 A19.T1 223.11,224.99 221.89,223.77 212.95,223.77 211.73,224.99 A20.T1
  Bottom 0.508: 387.3,227.03 388.52,225.81 AB06.AT1 | 387.3,227.03 399.9,227.03 401.12,225.81 AB05.AT1 402.34,225.81 402.74,225.81 403.96,227.03 412.5,227.03 | 412.5,227.03 413.71,225.81 AB04.AT1 | A36.C2 5.28,267.26 6.1,268.07 15.04,268.07 16.26,266.85 16.66,266.85 A35.C2 17.88,266.04 18.69,265.23 28.85,265.23 29.67,266.04 A34.C2 30.89,266.85 32.11,268.07 39.01,268.07 40.23,266.85 42.27,266.85 A33.C2 43.48,266.85 44.7,268.07 53.65,268.07 | A28A.D2 102.41,263.6 100.79,263.6 98.75,265.63 95.1,265.63 94.28,266.45 AB29.AC2 93.07,267.26 89,267.26 88.19,268.07 85.34,268.07 84.12,266.85 81.69,266.85 AB30.AC2 80.47,267.26 79.65,268.07 66.24,268.07 | 53.65,268.07 54.86,266.85 A32.C2 | 66.24,268.07 67.46,266.85 AB31.AC2 | 66.24,268.07 53.65,268.07 | A23.C2 169.06,266.45 167.44,264.82 164.59,264.82 163.37,263.6 160.93,263.6 A24.D1 | B24.C2 157.68,197.36 158.09,197.76 162.15,197.76 162.56,198.17 165.81,198.17 167.03,196.95 169.06,196.95 B23.C2 170.28,197.36 170.69,197.76 174.75,197.76 175.16,198.17 205.23,198.17 206.45,196.95 207.26,196.95 B20.C2 208.48,197.36 212.55,197.36 213.36,198.17 215.8,198.17 217.02,196.95 219.86,196.95 B19.C2 221.08,197.36 221.49,197.76 225.55,197.76 225.96,198.17 235.31,198.17 | A24.T1 160.93,225.81 162.15,227.03 171.09,227.03 172.31,225.81 A23.T1 | 235.31,198.17 234.09,196.95 B18.C2 | 235.31,198.17 240.59,198.17 241.4,197.36 245.47,197.36 B17.C2 246.69,197.36 247.09,197.76 251.16,197.76 251.56,198.17 260.1,198.17 | 361.7,198.17 362.1,198.58 368.2,198.58 369.01,199.39 369.42,199.39 AB07.BB2 | 361.7,198.17 360.88,197.36 B08.C2
  Bottom 0.508: 361.7,198.17 353.16,198.17 352.75,197.76 348.69,197.76 348.29,197.36 B09.C2 347.07,196.95 345.85,196.95 344.63,198.17 336.91,198.17 335.69,196.95 B10.C2 334.47,196.95 330.81,196.95 329.59,198.17 320.24,198.17 | 260.1,198.17 259.28,197.36 B16.C2 | 269.44,198.17 260.1,198.17 | 269.44,198.17 270.66,196.95 B15.C2 | 282.85,198.17 283.67,197.36 B14.C2 | 282.85,198.17 269.44,198.17 | 295.45,198.17 296.27,197.36 B13.C2 | 295.45,198.17 282.85,198.17 | 295.45,198.17 307.64,198.17 308.86,196.95 B12.C2 310.08,197.36 311.3,197.36 312.12,198.17 320.24,198.17 | 320.24,198.17 321.46,196.95 B11.C2 | A28A.C2 106.88,266.45 108.1,265.23 154.84,265.23 156.06,266.45 156.46,266.45 A24.C2
GO\  (via drill 0.61)
  Top 0.203: v356.82,97.79 356.41,98.2 356.41,101.45 C08.N2 356.82,102.26 356.01,103.07 356.01,150.62 | 356.01,150.62 356.01,154.28 356.82,155.09 B08.T2 | 356.01,150.62 v356.41,150.62
  Route2 0.203: v356.82,97.79 319.84,60.81 316.59,60.81 D12.C1
  Route15 0.203: v306.83,151.03 296.27,161.59 294.23,161.59 B13.R2
  Bottom 0.203: v306.83,151.03 321.46,151.03 325.12,147.37 330,147.37 330.81,146.56 347.47,146.56 348.29,147.37 353.16,147.37 v356.41,150.62
HSR_RUN\
  Top 0.203: AB30.AK1 87.78,248.16 92.25,248.16 93.07,248.97 95.1,248.97 95.1,216.05 97.94,213.21 97.94,203.05 95.5,200.61 95.5,164.03 93.88,162.41 93.88,159.56 AB29.BS2
HZ880
  Top 0.203: C33.P2 42.67,99.01 41.45,100.23 41.45,112.01 39.83,113.64 C33.J2
ILLEGAL_REF\  (via drill 0.61)
  Top 0.203: v432.82,159.16 433.63,158.34 433.63,157.12 434.04,156.72 434.85,156.72 434.85,128.27 434.04,127.46 C02.D2 | v383.64,58.37 384.05,58.78 384.05,80.72 382.83,81.94 C06.V2
  Route2 0.203: v396.65,86 403.96,93.32 403.96,94.13 432.82,122.99 432.82,125.83 433.22,126.24 C02.D2
  Route15 0.203: v330.81,261.57 336.5,255.88 336.5,254.66 339.34,251.82 339.34,247.75 340.97,246.13 345.85,246.13 357.23,234.75 357.23,233.53 358.44,232.31 358.44,231.5 358.85,231.09 360.88,231.09 v432.82,159.16 | v437.29,57.15 443.38,51.05 445.41,51.05 D01.F2
  Bottom 0.203: v396.65,86 395.02,84.38 384.86,84.38 383.24,82.75 C06.V2 | v330.81,261.57 330.4,261.98 322.68,261.98 319.84,264.82 318.62,264.82 316.18,262.38 311.71,262.38 309.27,264.82 301.95,264.82 300.74,263.6 A13.D1 | v437.29,57.15 437.29,59.18 419.81,59.18 419.4,58.78 384.05,58.78 v383.64,58.37
IN_STOP2\
  Top 0.203: D32.V2 52.02,13.26 51.21,14.07 51.21,23.83 52.02,24.64 D32.R2
INHIBIT  (via drill 0.61)
  Top 0.203: v266.19,29.92 266.6,30.33 266.6,112.01 v264.97,113.64
  Bottom 0.203: v266.19,29.92 260.1,29.92 259.28,29.11 D16.P2 | v264.97,113.64 266.6,115.27 267.41,115.27 267.82,115.67 275.54,115.67 277.17,117.3 C15.H1
INHIBIT\
  Top 0.203: D16.R2 254.81,25.45 252.78,27.48 252.78,27.89 D17.P1 | D17.D2 243.43,56.74 245.47,54.71 245.47,54.3 D17.E2 245.47,53.49 245.47,53.09 243.43,51.05 D17.F2 | D17.R1 248.72,25.86 247.9,26.67 247.9,42.52 245.87,44.55 245.87,46.99 D17.H2
  Bottom 0.203: D17.R1 249.94,25.86 251.97,27.89 D17.P1 | D17.F2 243.43,50.24 245.47,48.21 245.87,48.21 D17.H2
INITIALIZE  (via drill 0.61)
  Top 0.203: v67.06,50.65 67.87,51.46 67.87,53.49 D31.E2 | v120.7,53.09 120.29,53.49 120.29,72.19 118.26,74.22 118.26,77.88 120.29,79.91 120.29,90.07 119.08,91.29 C27.S2 | v436.07,20.57 435.25,21.39 435.25,33.58 436.07,34.39 D02.M2
  Route15 0.203: v446.63,41.71 444.19,44.15 444.19,48.21 431.6,60.81 431.6,67.72 420.22,79.1 420.22,81.13 401.93,99.42 401.93,101.04 C05.N1 | v268.22,52.68 269.44,53.9 293.01,30.33 297.89,30.33 v304.39,23.83
  Bottom 0.203: 65.84,49.43 53.65,49.43 52.83,50.24 D32.F2 | 65.84,49.43 v67.06,50.65 | 120.7,49.43 v120.7,53.09 | 120.7,49.43 65.84,49.43 | v446.63,41.71 440.13,35.2 437.29,35.2 D02.M2 | 120.7,49.43 175.97,49.43 179.22,52.68 v268.22,52.68 | v304.39,23.83 304.8,23.42 338.12,23.42 340.97,20.57 358.04,20.57 358.44,20.17 362.51,20.17 362.92,20.57 v436.07,20.57
INITIALIZE\  (via drill 0.61)
  Top 0.203: v388.11,103.07 387.71,103.48 387.71,104.7 | 387.71,104.7 387.71,114.45 v387.3,114.86 | v390.14,117.7 390.55,118.11 390.55,134.77 391.77,135.99 C06.A1 | v402.74,29.52 400.3,29.52 400.3,49.02 396.65,52.68 396.65,64.06 390.96,69.75 390.96,99.01 390.14,99.82 390.14,102.26 387.71,104.7 | v89.41,221.34 89,220.93 89,166.88 87.78,165.66 AB30.BP1 86.97,164.44 86.16,163.63 86.16,140.46 82.91,137.21 82.91,88.04 81.28,86.41 C30.U2
  Route2 0.203: v390.14,117.7 v387.3,114.86 | C30.V2 78.44,82.75 78.44,83.16 80.47,85.19 C30.U2
  Route15 0.203: v320.65,28.3 319.02,28.3 288.14,59.18 287.73,59.18 v286.92,60 | v91.85,68.12 78.03,81.94 C30.V2
  Bottom 0.203: v388.11,103.07 384.45,103.07 383.24,101.85 C06.N2 | D02.N2 432.82,31.55 431.6,30.33 420.22,30.33 419.4,31.14 415.75,31.14 414.53,29.92 403.15,29.92 v402.74,29.52 402.34,29.52 401.93,29.92 321.46,29.92 320.65,29.11 v320.65,28.3 | v89.41,221.34 89,220.93 85.34,220.93 85.34,223.77 85.75,224.18 86.16,224.18 86.16,227.03 85.75,227.43 69.49,227.43 68.68,228.24 AB31.AS2 | v286.92,60 286.11,59.18 185.72,59.18 182.88,62.03 165,62.03 164.59,62.43 161.34,62.43 160.93,62.03 152.4,62.03 149.15,65.28 97.13,65.28 94.28,68.12 v91.85,68.12
INPUT_BUS00  (via drill 0.61)
  Top 0.203: v378.36,151.03 377.95,151.44 377.95,173.79 379.58,175.41 379.58,177.04 AB07.BK1
  Route2 0.203: v321.46,25.04 322.68,23.83 323.9,25.04 323.9,27.48 330,33.58 331.62,33.58 340.56,42.52 345.85,42.52 371.86,68.53 371.86,68.94 391.36,88.44 391.36,89.26 393.39,91.29 393.39,94.13 v393.8,94.54 | v368.61,137.62 368.61,139.24 373.48,144.12 373.48,148.59 375.51,150.62 377.95,150.62 v378.36,151.03
  Route15 0.203: v321.46,25.04 309.68,36.83 305.61,36.83 294.23,48.21 294.23,50.24 D13.F2 | v393.8,94.54 384.45,103.89 384.45,115.27 382.42,117.3 382.42,118.92 381.2,120.14 381.2,124.61 370.64,135.18 370.64,135.59 v368.61,137.62
INPUT_BUS01  (via drill 0.61)
  Top 0.203: v380.39,121.36 381.2,122.17 381.2,145.75 384.05,148.59 v384.05,170.94
  Route2 0.203: v320.24,42.11 320.24,42.52 321.46,43.74 322.68,43.74 334.06,55.12 338.12,55.12 353.97,70.97 353.97,71.37 361.29,78.69 362.1,78.69 362.51,79.1 364.13,79.1 v382.02,96.98 | v376.73,118.11 377.14,118.11 v380.39,121.36
  Route15 0.203: v382.02,96.98 382.02,100.23 375.11,107.14 375.11,116.48 v376.73,118.11
  Bottom 0.203: v320.24,42.11 319.84,42.52 295.86,42.52 294.23,44.15 D13.J2 | v384.05,170.94 379.98,170.94 AB07.BM1
INPUT_BUS02  (via drill 0.61)
  Top 0.203: v295.05,29.52 295.05,36.83 294.23,37.64 D13.L2 | v390.55,26.26 393.39,26.26 393.39,37.24 392.58,38.05 392.58,39.68 393.39,40.49 v393.39,63.25 | v372.67,115.67 374.29,115.67 374.29,137.62 373.89,138.02 373.89,151.03 374.7,151.84 374.7,162.41 375.92,163.63 375.92,166.47 375.11,167.28 375.11,171.75 378.76,175.41 v378.76,176.22
  Route2 0.203: v358.85,101.04 358.85,105.51 364.95,111.61 365.35,111.61 369.42,115.67 v372.67,115.67
  Route15 0.203: v393.39,63.25 368.61,88.04 368.61,92.1 367.39,93.32 363.32,93.32 358.85,97.79 v358.85,101.04
  Bottom 0.203: v295.05,29.52 295.05,27.08 348.69,27.08 349.1,26.67 390.14,26.67 v390.55,26.26 | v378.76,176.22 379.58,175.41 381.2,175.41 382.02,176.22 390.14,176.22 390.55,175.82 391.36,175.82 391.77,176.22 391.77,177.04 AB06.BK1
INPUT_BUS03  (via drill 0.61)
  Route2 0.203: v351.13,8.79 362.51,8.79 373.89,20.17 375.51,20.17 378.76,23.42 384.86,23.42 v447.04,85.6
  Route15 0.203: v351.13,8.79 335.69,24.23 311.71,24.23 308.86,27.08 302.77,27.08 299.92,29.92 299.11,29.92 297.89,31.14 294.23,31.14 D13.N2 | v447.04,85.6 447.04,86 438.51,94.54 438.51,100.63 427.13,112.01 427.13,112.42 426.72,112.83 426.31,112.83 425.91,113.23 425.91,118.52 409.65,134.77 409.65,135.59 403.56,141.68 403.56,142.09 398.27,147.37 398.27,150.62 397.05,151.84 397.05,164.44 393.8,167.69 393.8,169.72 392.58,170.94 AB06.BM1
INPUT_BUS04  (via drill 0.61)
  Top 0.203: v95.1,271.73 95.1,275.39 68.68,275.39 63.8,270.51 63.8,262.79 62.18,261.16 A32.E1 | v211.33,272.95 213.77,275.39 v227.58,275.39 | v254.41,276.61 257.25,279.45 257.25,284.33 293.01,284.33 v293.01,281.48 | v320.24,270.92 321.06,271.73 321.06,279.45 324.71,283.11 364.54,283.11 364.54,279.45 366.17,277.83 370.64,277.83 370.64,275.79 386.89,275.79 386.89,281.08 388.52,282.7 441.76,282.7 441.76,271.32 v443.38,269.7
  Route2 0.203: v443.38,269.7 456.39,256.69 454.36,254.66 454.36,231.5 448.26,225.4 448.26,224.18 444.19,220.12 444.19,219.3 406.81,181.91 406.81,179.88 405.18,178.26 AB05.BK1
  Route15 0.203: v293.01,281.48 301.95,281.48 302.77,280.67 305.61,280.67 314.96,271.32 319.84,271.32 v320.24,270.92
  Bottom 0.203: v95.1,271.73 95.5,271.32 98.75,271.32 99.16,270.92 101.19,270.92 102.01,271.73 161.75,271.73 162.56,270.92 165.81,270.92 166.62,271.73 210.11,271.73 v211.33,272.95 | v227.58,275.39 228.4,276.2 254,276.2 v254.41,276.61
INPUT_BUS05  (via drill 0.61)
  Top 0.203: v380.8,269.7 375.51,274.98 370.23,274.98 370.23,276.2 369.01,277.42 362.92,277.42 362.92,282.3 362.51,282.7 325.12,282.7 v325.12,279.86 | v273.1,279.86 272.29,280.67 267.82,280.67 267.82,272.14 v266.19,270.51
  Route2 0.203: v434.04,203.86 421.03,190.86 421.03,189.64 405.18,173.79 405.18,172.16 AB05.BM1 | v266.19,270.51 265.38,270.51 258.88,264.01 258.88,262.38 v234.09,237.59 | v80.87,268.48 67.87,268.48 54.05,254.66 54.05,252.63 52.83,251.41 A32.J2
  Route15 0.203: v434.04,203.86 434.04,215.24 421.44,227.84 421.44,229.06 409.65,240.84 409.65,244.91 396.24,258.32 392.18,258.32 v380.8,269.7 | v234.09,237.59 232.87,237.59 221.49,248.97 195.88,248.97 v181.66,263.2
  Bottom 0.203: v325.12,279.86 323.9,278.64 315.37,278.64 314.55,279.45 312.52,279.45 312.12,279.86 v273.1,279.86 | v181.66,263.2 180.85,262.38 106.48,262.38 100.79,268.07 89,268.07 88.19,268.88 85.34,268.88 84.94,268.48 v80.87,268.48
INPUT_BUS06  (via drill 0.61)
  Top 0.203: v160.53,279.04 166.22,284.73 450.7,284.73 450.7,233.53 v449.07,231.9 | v418.59,199.8 419,199.39 419,179.07 418.19,178.26 AB04.BK1
  Route2 0.203: v160.53,279.04 155.65,274.17 154.03,274.17 135.33,255.47 131.27,255.47 120.29,244.5 99.97,264.82 77.22,264.82 69.9,257.5 69.09,257.5 59.33,247.75 59.33,244.91 A32.L1 | v449.07,231.9 449.07,231.5 447.45,229.87 447.45,228.65 424.69,205.89 424.69,205.49 423.88,204.67 423.47,204.67 v418.59,199.8
INPUT_BUS07  (via drill 0.61)
  Route2 0.203: v117.04,239.22 97.94,258.32 83.31,258.32 72.34,247.34 69.9,247.34 66.65,244.09 66.65,243.28 58.93,235.56 56.08,235.56 A32.P2 | v345.44,85.19 345.44,85.6 356.82,96.98 357.23,96.98 357.63,97.38 357.63,98.6 365.76,106.73 365.76,107.14 367.39,108.76 368.2,108.76 v372.67,113.23 | v383.24,117.7 383.24,119.33 399.9,135.99 399.9,138.02 425.09,163.22 425.5,163.22 425.91,163.63 425.91,165.25 419,172.16 418.19,171.35 AB04.BM1
  Route15 0.203: v117.04,239.22 117.04,238.81 118.67,237.19 121.11,237.19 121.51,236.78 125.58,236.78 128.42,233.93 130.86,233.93 162.97,201.83 167.84,201.83 184.51,185.17 185.72,185.17 223.11,147.78 226.77,147.78 230.02,144.53 234.49,144.53 257.25,121.77 257.25,120.95 260.1,118.11 260.1,114.05 267.41,106.73 273.1,106.73 278.38,101.45 279.2,101.45 280.42,100.23 284.89,100.23 v292.61,92.51 | v303.17,87.63 v300.33,90.47
  Bottom 0.203: v292.61,92.51 293.83,91.29 294.64,91.29 295.45,90.47 v300.33,90.47 | v303.17,87.63 303.58,87.22 343.81,87.22 345.44,85.6 v345.44,85.19 | v372.67,113.23 373.07,112.83 376.73,112.83 379.17,115.27 380.8,115.27 v383.24,117.7
INPUT_BUS08  (via drill 0.61)
  Top 0.203: v85.34,226.62 89,226.62 v89,235.15 | v290.17,133.55 291.8,131.93 291.8,102.67 290.98,101.85 290.98,101.04 292.2,99.82 292.2,94.54 v294.23,92.51
  Route2 0.203: v319.43,92.1 327.56,100.23 327.56,100.63 327.96,101.04 329.18,101.04 v336.09,107.95 | v344.22,109.58 350.32,115.67 354.38,115.67 374.29,135.59 374.29,136.8 388.11,150.62 394.21,150.62 419.4,175.82 427.94,175.82 429.56,177.44 AB03.BK1
  Route15 0.203: v169.47,231.09 172.31,228.24 173.13,228.24 186.94,214.43 186.94,207.11 188.16,205.89 195.48,205.89 204.83,196.54 204.83,195.73 228.4,172.16 228.4,166.88 255.63,139.65 255.63,137.62 v258.47,134.77
  Bottom 0.203: v85.34,226.62 68.28,226.62 67.06,227.84 62.99,227.84 62.59,228.24 A32.S1 | v89,235.15 90.63,233.53 167.03,233.53 v169.47,231.09 | v258.47,134.77 261.31,131.93 276.35,131.93 279.2,134.77 288.95,134.77 v290.17,133.55 | v294.23,92.51 295.86,90.88 299.52,90.88 299.92,91.29 301.95,91.29 302.36,90.88 305.61,90.88 306.02,91.29 308.46,91.29 308.86,90.88 318.21,90.88 v319.43,92.1 | v336.09,107.95 337.72,109.58 v344.22,109.58
INPUT_BUS09  (via drill 0.61)
  Top 0.203: v436.07,149.81 437.29,148.59 437.29,137.62 437.69,137.21 437.69,107.95 435.25,105.51 v435.25,55.12 | v189.38,113.64 187.35,115.67 v187.35,244.09
  Route2 0.203: v435.25,55.12 435.25,54.71 432,51.46 432,47.4 v393.8,9.2 | v75.59,244.5 54.05,222.96 54.05,220.93 52.83,219.71 A32.V2
  Route15 0.203: v436.07,149.81 435.25,150.62 435.25,157.94 431.6,161.59 431.6,165.66 430.78,166.47 430.78,170.94 AB03.BM1 | v302.77,5.54 298.3,5.54 293.42,10.41 292.61,10.41 v189.38,113.64
  Bottom 0.203: v393.8,9.2 392.18,7.57 310.49,7.57 308.46,5.54 v302.77,5.54 | v187.35,244.09 187.35,245.72 76.81,245.72 v75.59,244.5
INPUT_BUS10  (via drill 0.61)
  Top 0.203: v282.04,157.53 282.85,158.34 282.85,167.69 v284.07,168.91
  Route2 0.203: v359.66,128.68 362.1,128.68 370.64,137.21 370.64,139.24 376.73,145.34 376.73,146.56 v405.59,175.41
  Route15 0.203: v129.24,247.75 159.31,217.68 160.12,217.68 164.59,213.21 164.59,212.39 v217.42,159.56 | v284.07,168.91 299.11,153.87 299.11,153.47 312.52,140.06 312.52,138.02 321.87,128.68 326.75,128.68 v328.78,126.64
  Bottom 0.203: v129.24,247.75 128.42,247.75 117.86,258.32 83.31,258.32 82.09,257.1 79.25,257.1 79.25,257.91 78.84,258.32 52.02,258.32 49.99,260.35 A33.E1 | v217.42,159.56 217.02,159.97 207.26,159.97 206.45,159.16 206.45,157.12 239.78,157.12 240.18,157.53 273.1,157.53 273.91,158.34 276.35,158.34 277.17,157.53 v282.04,157.53 | v328.78,126.64 330.4,128.27 336.09,128.27 336.5,127.86 337.31,127.86 337.72,128.27 345.85,128.27 347.47,126.64 349.1,126.64 349.91,125.83 353.97,125.83 356.82,128.68 v359.66,128.68 | v405.59,175.41 406.81,176.63 441.35,176.63 442.16,177.44 AB02.BK1
INPUT_BUS11  (via drill 0.61)
  Top 0.203: v106.48,284.33 76,284.33 63.4,271.73 44.3,271.73 41.45,268.88 41.45,257.1 39.83,255.47 39.83,251.41 A33.J2 | v442.16,262.38 441.76,261.98 441.76,216.86 440.94,216.05 440.94,201.83 441.35,201.42 441.35,172.57 v440.94,172.16
  Route2 0.203: v278.79,262.79 278.79,263.2 290.17,274.57 293.01,274.57 293.42,274.98 299.92,274.98 v306.43,281.48 | v345.44,259.13 348.69,259.13 351.94,262.38 358.44,262.38 371.04,274.98 373.07,274.98 375.51,272.54 v370.23,267.26
  Route15 0.203: v106.48,284.33 227.99,284.33 228.4,284.73 248.31,284.73 251.97,281.08 253.19,281.08 254,280.26 258.47,280.26 261.72,277.01 264.57,277.01 v278.79,262.79 | v306.43,281.48 306.43,281.08 314.55,272.95 314.55,272.54 315.37,271.73 332.84,271.73 v345.44,259.13
  Bottom 0.203: v370.23,267.26 367.79,264.82 367.79,261.98 441.76,261.98 v442.16,262.38 | v440.94,172.16 441.35,171.75 442.16,171.75 AB02.BM1
INT_DELAY  (via drill 0.61)
  Top 0.203: v293.01,135.18 292.61,135.59 292.61,148.18 v291.8,149
  Route2 0.203: v293.01,135.18 286.11,128.27 286.11,126.64 285.29,125.83 286.92,124.21 287.73,124.21 290.17,126.64 293.01,126.64 C13.D2 | v291.8,149 291.8,149.4 309.68,167.28 309.68,169.32 317.4,177.04 317.4,179.07 318.62,180.29 B11.J2
INT_ENABLE
  Bottom 0.203: B11.F2 319.84,187.2 324.71,187.2 B11.F1
INT_ENABLE\  (via drill 0.61)
  Route15 0.203: v399.08,147.78 409.65,137.21 409.65,136.4 410.06,135.99 410.06,135.18 447.04,98.2 447.04,96.98 448.67,95.35 448.67,92.51 C01.S2 | v385.27,150.62 384.86,150.62 v345.44,190.04
  Bottom 0.203: B11.E2 322.68,190.45 327.96,190.45 B11.E1 329.18,190.86 330,191.67 343.81,191.67 v345.44,190.04 | v399.08,147.78 396.24,150.62 v385.27,150.62
INT_INHIBIT\  (via drill 0.61)
  Top 0.203: v132.08,119.33 132.08,123.39 C26.E2
  Route2 0.203: v269.85,120.14 269.85,118.52 v267.82,116.48
  Route15 0.203: v62.18,107.14 43.89,125.42 43.89,125.83 23.98,145.75 23.98,149 21.13,151.84 23.16,153.87 23.16,155.91 14.22,164.85 14.22,165.66 9.75,170.13 9.75,172.57 8.53,173.79 8.53,174.19 B36.L1
  Bottom 0.203: v269.85,120.14 271.88,122.17 291.8,122.17 293.01,120.95 C13.F2 | v267.82,116.48 267,115.67 254,115.67 251.16,112.83 138.58,112.83 134.11,117.3 | 134.11,117.3 v132.08,119.33 | v62.18,107.14 62.59,106.73 93.47,106.73 96.32,109.58 126.39,109.58 134.11,117.3
INT_IO_BUS4\
  Top 0.203: A32.D1 58.52,264.01 58.52,269.29 A32.B1
  Route15 0.203: AB30.AP2 80.47,235.56 80.47,238 70.31,248.16 70.31,249.78 60.55,259.54 60.55,261.16 58.93,262.79 A32.D1
INT_IO_BUS5\
  Top 0.203: A32.H2 55.27,254.66 55.27,259.54 A32.E2
  Route15 0.203: AB30.AS2 80.47,229.06 80.47,231.09 78.44,233.12 73.15,233.12 70.71,235.56 70.71,236.78 57.3,250.19 57.3,252.22 56.08,253.44 A32.H2
INT_IO_BUS6\  (via drill 0.61)
  Top 0.203: A32.H1 61.37,253.44 61.37,248.16 A32.K1 62.18,248.16 v63.4,249.38 | v82.91,249.78 82.91,233.12 83.72,232.31 AB30.AR1
  Bottom 0.203: v82.91,249.78 82.5,249.38 v63.4,249.38
INT_IO_BUS7\
  Top 0.203: A32.N2 52.02,238.81 52.02,243.69 A32.L2
  Bottom 0.203: AB30.AN2 77.22,237.59 76.81,237.19 72.34,237.19 71.93,236.78 53.65,236.78 52.83,237.59 A32.N2
INT_IO_BUS8\
  Top 0.203: A32.R1 58.12,232.31 58.12,237.59 A32.N1
  Bottom 0.203: AB30.AS1 86.56,228.65 84.94,230.28 60.55,230.28 59.33,231.5 A32.R1
INT_IO_BUS9\  (via drill 0.61)
  Top 0.203: A32.U2 55.27,222.96 55.27,227.84 A32.S2 56.08,229.06 56.08,233.12 v56.49,233.53
  Bottom 0.203: v56.49,233.53 85.34,233.53 86.56,234.75 AB30.AP1
INT_IO_BUS10\
  Top 0.203: A33.D1 45.52,264.01 45.52,269.29 A33.B1
  Route15 0.203: AB30.AR2 77.22,232.31 73.15,232.31 62.18,243.28 62.18,244.5 56.9,249.78 56.9,250.6 47.95,259.54 47.95,261.16 46.33,262.79 A33.D1
INT_IO_BUS11\  (via drill 0.61)
  Top 0.203: A33.H2 42.67,254.66 42.67,259.54 A33.E2 | v81.69,250.19 81.69,249.78 82.5,248.97 82.5,230.28 84.53,230.28 85.34,231.09 85.34,236.78 84.53,237.59 AB30.AN1
  Bottom 0.203: v81.69,250.19 79.65,252.22 45.52,252.22 43.89,253.85 43.48,253.85 A33.H2
INT_OK  (via drill 0.61)
  Top 0.203: 305.21,151.03 305.21,166.06 306.02,166.88 306.02,167.69 B12.N2 | 305.21,151.03 305.21,148.18 306.43,146.96 306.43,142.9 305.21,141.68 v305.21,106.73 305.21,106.32 305.21,81.53 306.02,80.72 306.02,70.56 307.64,68.94 307.64,45.77 306.83,44.96 D12.J2 | 305.21,151.03 v305.61,151.03
  Bottom 0.203: v305.21,106.73 269.85,106.73 269.04,107.54 C15.L2 | v305.61,151.03 298.7,151.03 297.49,152.25 B13.U2
INT_OK\  (via drill 0.61)
  Top 0.203: v344.22,92.51 344.22,89.66 C09.T2 | v291.39,150.22 290.98,149.81 290.98,138.02 292.2,136.8 292.2,116.08 293.42,114.86 C13.J2
  Route2 0.203: v291.39,150.22 309.27,168.1 309.27,170.94 B12.M2
  Route15 0.203: v344.22,92.51 324.71,112.01 v324.71,112.42
  Bottom 0.203: C13.J2 294.23,114.05 299.52,114.05 C13.J1 300.74,114.05 303.99,114.05 305.21,112.83 324.31,112.83 v324.71,112.42
INT_RQST  (via drill 0.61)
  Top 0.203: v99.16,176.22 102.01,173.38 102.01,128.27 102.82,127.46 C28.D2
  Route15 0.203: v99.16,176.22 66.24,209.14 66.24,211.58 60.15,217.68 60.15,219.71 45.11,234.75 43.48,234.75 A33.P2
INT_SKIP_EN\  (via drill 0.61)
